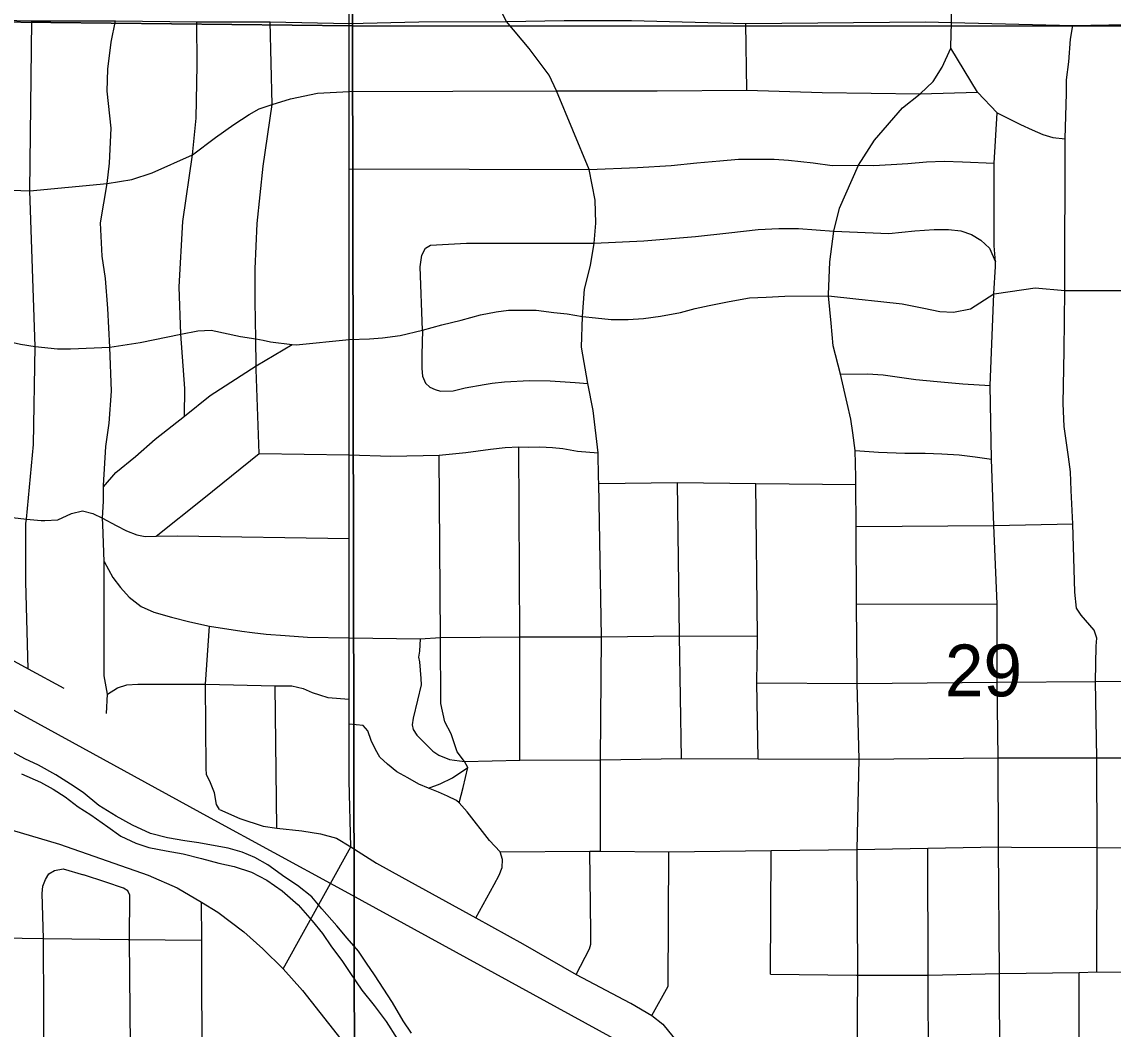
# Model space of a CAD drawing. Extents: x 0 to 34, y 0 to 22.
# Drawn here: x 3.784 to 4.664, y 18.692 to 19.505 of the extents above; entities that cross this region are included whole.
import ezdxf

# ---------------------------------------------------------------- set-up
doc = ezdxf.new("R2010")
doc.units = 0
for name, color, linetype in [('GM_X_City_Street', 7, 'Continuous'), ('GM_X_County_Road', 7, 'Continuous'), ('GM_X_Minor_River', 7, 'Continuous'), ('GM_X_Rail_Line', 7, 'Continuous'), ('GM_X_Section', 7, 'Continuous'), ('GM_X_Section_Text', 7, 'Continuous')]:
    doc.layers.add(name, color=color, linetype=linetype)

msp = doc.modelspace()

# ---------------------------------------------------------------- linework, layer by layer
at = {"layer": 'GM_X_City_Street'}
for p, q in [((4.36899, 19.44986), (4.36805, 19.50372)), ((4.45735, 19.03517), (4.57094, 19.03531)), ((3.98987, 18.85427), (3.98842, 18.96911)), ((4.38793, 18.73648), (4.3886, 18.83632)), ((3.89964, 18.76435), (3.9294, 18.76407)), ((4.38793, 18.73648), (4.45746, 18.73577)), ((4.27536, 18.71305), (4.29227, 18.7032))]:
    msp.add_line(p, q, dxfattribs=at)
for points in [[(4.21534, 19.44926), (4.20947, 19.46187), (4.19338, 19.48352), (4.17513, 19.50518), (4.16591, 19.52327), (4.16076, 19.54117), (4.15845, 19.55941), (4.15556, 19.60002), (4.1545, 19.61367), (4.15125, 19.6552), (4.15125, 19.65606), (4.15323, 19.70997), (4.15729, 19.74229), (4.16073, 19.77161), (4.16742, 19.83163), (4.16936, 19.86473), (4.16715, 19.89331), (4.16377, 19.93656), (4.1588, 19.97307), (4.15568, 20.0293), (4.1563, 20.06684)], [(3.55615, 19.50881), (3.61303, 19.50805), (3.6739, 19.50718), (3.73172, 19.50718), (3.79215, 19.50588), (3.85954, 19.50588), (3.92519, 19.50501), (3.98431, 19.50501), (4.04819, 19.5037), (4.10439, 19.50509), (4.17513, 19.50518), (4.22153, 19.5061), (4.27577, 19.50611), (4.36805, 19.50372), (4.51295, 19.50505), (4.53405, 19.50437), (4.63184, 19.50201), (4.6753, 19.50298), (4.75176, 19.50458), (4.76019, 19.50475), (4.80108, 19.50436), (4.86718, 19.50405), (4.91274, 19.50445)], [(3.78914, 18.9829), (3.7874, 19.05322), (3.7874, 19.10015), (3.78774, 19.10376), (3.79342, 19.16393), (3.79479, 19.24313), (3.79051, 19.36859), (3.79215, 19.50588)], [(3.84998, 19.13087), (3.85186, 19.16229), (3.85445, 19.18111), (3.85641, 19.20705), (3.8552, 19.24251), (3.85354, 19.27363), (3.85155, 19.29802), (3.84892, 19.31583), (3.8476, 19.34286), (3.85285, 19.37456), (3.85485, 19.39099), (3.85617, 19.41934), (3.85288, 19.449), (3.85354, 19.46681), (3.85617, 19.48857), (3.85954, 19.50588)], [(3.91532, 19.18672), (3.91562, 19.2092), (3.91249, 19.2531), (3.91103, 19.29109), (3.91409, 19.3439), (3.92183, 19.39777), (3.92481, 19.42732), (3.92557, 19.47017), (3.92519, 19.50501)], [(3.97549, 19.15676), (3.97323, 19.22437), (3.97319, 19.22747), (3.9729, 19.24936), (3.97243, 19.27938), (3.97243, 19.30569), (3.97402, 19.34237), (3.97881, 19.38861), (3.98616, 19.43823), (3.98431, 19.50501)], [(4.65121, 18.73849), (4.65155, 18.83884), (4.65114, 18.91116), (4.65026, 18.97268), (4.65062, 19.00126), (4.65133, 19.00769), (4.64919, 19.01412), (4.63847, 19.02627), (4.63491, 19.03198), (4.63348, 19.04483), (4.63198, 19.09987), (4.63062, 19.12697), (4.62991, 19.14197), (4.62848, 19.15411), (4.6249, 19.1784), (4.62419, 19.19697), (4.6249, 19.23983), (4.62534, 19.28832), (4.62573, 19.4106), (4.62669, 19.44761), (4.62669, 19.45815), (4.62866, 19.47264), (4.62998, 19.49108), (4.63184, 19.50201)], [(4.57279, 18.73709), (4.57177, 18.83936), (4.5717, 18.91116), (4.57083, 18.97212), (4.57094, 19.03531), (4.56807, 19.09855), (4.56615, 19.15221), (4.56519, 19.21161), (4.56822, 19.2856), (4.56961, 19.30758), (4.56935, 19.31144), (4.5685, 19.32438), (4.5685, 19.39101), (4.5709, 19.43152), (4.55484, 19.44835), (4.53342, 19.48379)], [(3.73239, 19.37081), (3.79051, 19.36859), (3.85285, 19.37456), (3.87275, 19.37788), (3.88933, 19.38318), (3.92183, 19.39777), (3.9404, 19.4117), (3.95499, 19.42231), (3.96759, 19.43027), (3.97555, 19.43491), (3.98616, 19.43823), (4.00075, 19.44287), (4.02264, 19.44751), (4.04819, 19.44884), (4.21534, 19.44926), (4.2966, 19.44926), (4.36899, 19.44986), (4.42963, 19.44809), (4.50866, 19.44693), (4.55484, 19.44835)], [(4.23637, 19.2673), (4.23792, 19.28927), (4.24287, 19.30844), (4.24584, 19.32655), (4.2472, 19.34247), (4.24658, 19.36103), (4.24164, 19.38577), (4.21534, 19.44926)], [(4.5709, 19.43152), (4.58977, 19.42208), (4.59896, 19.418), (4.60762, 19.41418), (4.61578, 19.41162), (4.62573, 19.4106)], [(4.57018, 19.28588), (4.60154, 19.29036), (4.62534, 19.28832), (4.68109, 19.28832), (4.75793, 19.28968), (4.77152, 19.29104), (4.78173, 19.29308), (4.79396, 19.29852), (4.82836, 19.32165), (4.85992, 19.3434), (4.89529, 19.36774), (4.92631, 19.38928), (4.97045, 19.41888)], [(4.0482, 19.3865), (4.24164, 19.38577), (4.28068, 19.38751), (4.30796, 19.38917), (4.32862, 19.39124), (4.34721, 19.39289), (4.3621, 19.39412), (4.39102, 19.39412), (4.40259, 19.3933), (4.42243, 19.39124), (4.43772, 19.38917), (4.45895, 19.38944), (4.47119, 19.38917), (4.48545, 19.38979), (4.49867, 19.39082), (4.51376, 19.39206), (4.52801, 19.39268), (4.54289, 19.39206), (4.5685, 19.39101)], [(4.10741, 19.25621), (4.10554, 19.30742), (4.10671, 19.3167), (4.10961, 19.32249), (4.11367, 19.32481), (4.14265, 19.32655), (4.24584, 19.32655), (4.28584, 19.32829), (4.32758, 19.33176), (4.35425, 19.33467), (4.37801, 19.33756), (4.39482, 19.33815), (4.41048, 19.33815), (4.43898, 19.33601), (4.48337, 19.33437), (4.50439, 19.33641), (4.52004, 19.33756), (4.53164, 19.33756), (4.54149, 19.33641), (4.55019, 19.3335), (4.55773, 19.32887), (4.56468, 19.32249), (4.56935, 19.31144)], [(4.23637, 19.2673), (4.24691, 19.26618), (4.25937, 19.26493), (4.27307, 19.26493), (4.28552, 19.26555), (4.29923, 19.26742), (4.31542, 19.27053), (4.32725, 19.27365), (4.33846, 19.27614), (4.35465, 19.27925), (4.37104, 19.28233), (4.38455, 19.28299), (4.39949, 19.28361), (4.43483, 19.28402)], [(4.43483, 19.28402), (4.45671, 19.28152), (4.47711, 19.27948), (4.49411, 19.27744), (4.51178, 19.27404), (4.5247, 19.27132), (4.53558, 19.27065), (4.54918, 19.27336), (4.56822, 19.2856), (4.57018, 19.28588)], [(3.97882, 19.24812), (3.98473, 19.24687), (4.00228, 19.24474), (4.00529, 19.24438), (4.0482, 19.24874), (4.06445, 19.24936), (4.07503, 19.24999), (4.08936, 19.25185), (4.10741, 19.25621), (4.12299, 19.26057), (4.13855, 19.26431), (4.15412, 19.26866), (4.16658, 19.27116), (4.17654, 19.2724), (4.18713, 19.2724), (4.19896, 19.2724), (4.21328, 19.27053), (4.22387, 19.26929), (4.23637, 19.2673)], [(3.55853, 19.2406), (3.61671, 19.24117), (3.63038, 19.24189), (3.64969, 19.24687), (3.6746, 19.25559), (3.68581, 19.26119), (3.69328, 19.26306), (3.70636, 19.26244), (3.72331, 19.26305), (3.73259, 19.26108), (3.7512, 19.2531), (3.76615, 19.24874), (3.78296, 19.245), (3.79479, 19.24313), (3.81285, 19.24127), (3.82344, 19.24127), (3.8552, 19.24251), (3.87948, 19.24624), (3.91249, 19.2531), (3.92619, 19.25559), (3.93678, 19.25621), (3.96045, 19.25123), (3.9729, 19.24936), (3.97882, 19.24812)], [(4.24936, 19.13745), (4.24901, 19.15729), (4.24503, 19.19146), (4.2407, 19.21318), (4.23551, 19.24244), (4.23637, 19.2673)], [(4.10741, 19.25621), (4.10666, 19.23636), (4.10666, 19.2252), (4.1072, 19.21921), (4.10965, 19.21349), (4.11319, 19.21022), (4.11755, 19.20832), (4.1219, 19.20696), (4.13198, 19.20723), (4.14179, 19.20968), (4.15704, 19.2124), (4.16357, 19.21349), (4.17338, 19.21458), (4.19353, 19.21567), (4.21014, 19.21539), (4.23056, 19.21403), (4.2407, 19.21318)], [(3.84992, 19.12986), (3.85987, 19.14136), (3.87583, 19.15438), (3.89179, 19.16824), (3.91532, 19.18672), (3.9359, 19.20353), (3.97319, 19.22747), (4.00228, 19.24474)], [(4.44435, 19.22076), (4.46633, 19.221), (4.47898, 19.22017), (4.5051, 19.21637), (4.52238, 19.21469), (4.54303, 19.213), (4.56519, 19.21161)], [(3.89241, 19.09004), (3.9309, 19.12069), (3.97549, 19.15676), (4.04821, 19.15554)], [(4.04821, 19.15554), (4.08187, 19.1547), (4.12071, 19.15528), (4.14228, 19.15758), (4.16213, 19.16017), (4.17393, 19.1616), (4.18486, 19.16218), (4.19292, 19.16189), (4.20183, 19.16218), (4.21219, 19.1616), (4.22053, 19.16074), (4.23233, 19.15872), (4.24901, 19.15729)], [(4.1369, 18.87473), (4.14001, 18.88719), (4.1438, 18.90337), (4.14123, 18.90808), (4.13514, 18.91589), (4.13029, 18.93045), (4.12543, 18.94016), (4.12197, 18.95506), (4.12174, 19.00821), (4.12071, 19.15528)], [(4.18589, 18.90913), (4.18569, 19.00871), (4.18486, 19.16218)], [(4.45639, 19.15917), (4.47518, 19.15779), (4.49625, 19.15695), (4.51268, 19.15695), (4.52617, 19.15653), (4.54008, 19.15569), (4.55314, 19.154), (4.56615, 19.15221)], [(3.50162, 19.14001), (3.55769, 19.11108), (3.61689, 19.07725), (3.66184, 19.05188), (3.73395, 19.01316), (3.78914, 18.9829), (3.81807, 18.96732)], [(3.84945, 19.09956), (3.84927, 19.10456), (3.84992, 19.11818), (3.84992, 19.12986), (3.84998, 19.13087)], [(4.25079, 18.83584), (4.2508, 18.90964), (4.25163, 19.00871), (4.24945, 19.13248), (4.24936, 19.13745)], [(4.24945, 19.13248), (4.31295, 19.13344), (4.37627, 19.13249), (4.45687, 19.13161)], [(4.31623, 18.91068), (4.3146, 19.0097), (4.31295, 19.13344)], [(4.37754, 19.00727), (4.37757, 19.0092), (4.37627, 19.13249)], [(3.67448, 19.10537), (3.68594, 19.1115), (3.69094, 19.11317), (3.69815, 19.11428), (3.71425, 19.11261), (3.73321, 19.11009), (3.78774, 19.10376), (3.79975, 19.10262), (3.80253, 19.10262), (3.81307, 19.10317), (3.82418, 19.10817), (3.83306, 19.11039), (3.84139, 19.10817), (3.84927, 19.10456), (3.86026, 19.09873), (3.86859, 19.09429), (3.87692, 19.09096), (3.88358, 19.08985), (3.89241, 19.09004), (3.90968, 19.09041), (4.04821, 19.08819)], [(3.85251, 18.94692), (3.85316, 18.9625), (3.85057, 18.97742), (3.85057, 19.06953), (3.84945, 19.09956)], [(4.45709, 19.09793), (4.56807, 19.09855), (4.63198, 19.09987)], [(3.85057, 19.06953), (3.85752, 19.05662), (3.86371, 19.04867), (3.87077, 19.04073), (3.88049, 19.03337), (3.89049, 19.02865), (3.90492, 19.02453), (3.91964, 19.021), (3.93554, 19.01747), (3.96145, 19.01335), (3.96999, 19.01217), (3.98117, 19.01099), (3.99648, 19.00981), (4.01444, 19.00864), (4.04822, 19.00805), (4.10538, 19.00722), (4.12174, 19.00821), (4.18569, 19.00871), (4.25163, 19.00871), (4.3146, 19.0097), (4.37757, 19.0092)], [(3.94367, 18.86951), (3.9411, 18.87358), (3.93939, 18.8829), (3.9357, 18.89219), (3.93299, 18.89733), (3.9327, 18.9028), (3.93231, 18.97062), (3.93554, 19.01747)], [(4.10538, 19.00722), (4.10474, 18.99716), (4.10396, 18.99246), (4.10474, 18.98854), (4.10592, 18.97524), (4.10631, 18.97015), (4.10318, 18.95762), (4.09965, 18.94315), (4.09887, 18.93767), (4.09965, 18.93414), (4.10279, 18.92945), (4.1157, 18.91653), (4.1204, 18.9134), (4.12901, 18.90988), (4.14123, 18.90808)], [(4.37802, 18.91047), (4.377, 18.97157), (4.37754, 19.00727)], [(4.377, 18.97157), (4.4579, 18.9712), (4.57083, 18.97212), (4.65026, 18.97268), (4.75912, 18.97379), (4.76412, 18.9799), (4.83411, 18.9799), (4.9213, 18.9799), (5.06741, 18.98086), (5.2073, 18.98068), (5.26798, 18.98362)], [(3.85316, 18.9625), (3.86121, 18.96767), (3.86892, 18.97008), (3.87759, 18.97056), (3.93231, 18.97062), (3.98842, 18.96911), (4.00191, 18.96911), (4.01106, 18.96719), (4.01829, 18.96381), (4.02408, 18.96189), (4.03082, 18.95996), (4.04822, 18.95851)], [(4.15031, 18.78206), (4.16502, 18.80883), (4.16916, 18.81642), (4.17158, 18.82263), (4.17193, 18.82919), (4.16989, 18.83539), (4.16123, 18.84437), (4.14329, 18.86748), (4.1369, 18.87473), (4.13466, 18.8768), (4.12742, 18.88025), (4.12017, 18.88335), (4.11223, 18.88663), (4.1043, 18.88991), (4.09533, 18.89508), (4.0867, 18.89992), (4.07911, 18.90613), (4.0729, 18.91165), (4.06945, 18.91786), (4.066, 18.9251), (4.06324, 18.93304), (4.05944, 18.93718), (4.04822, 18.93821)], [(4.14123, 18.90808), (4.18589, 18.90913), (4.2508, 18.90964), (4.31623, 18.91068), (4.37802, 18.91047), (4.45955, 18.91018), (4.5717, 18.91116), (4.65114, 18.91116), (4.75917, 18.91116), (4.83543, 18.91196), (4.92122, 18.91275), (4.96702, 18.91372)], [(4.11223, 18.88663), (4.12159, 18.89021), (4.13141, 18.89503), (4.1438, 18.90337)], [(3.94367, 18.86951), (3.96005, 18.86228), (3.97868, 18.856), (3.98987, 18.85427), (4.01004, 18.85219), (4.0251, 18.84979), (4.03792, 18.84643), (4.04943, 18.83941)], [(4.04943, 18.83941), (4.07021, 18.82608), (4.09062, 18.81486), (4.15031, 18.78206), (4.1881, 18.76118), (4.23126, 18.73624), (4.27451, 18.71354), (4.27536, 18.71305)], [(4.16989, 18.83539), (4.24235, 18.83593), (4.25079, 18.83584), (4.30612, 18.83525), (4.3886, 18.83632), (4.4579, 18.83722), (4.51483, 18.83829), (4.57177, 18.83936), (4.58228, 18.83901), (4.65155, 18.83884), (4.72759, 18.83852), (4.75872, 18.83927), (4.79711, 18.83902), (4.8355, 18.83877), (4.86353, 18.83848), (4.92138, 18.83961), (4.93209, 18.83982), (4.99657, 18.83982), (5.0671, 18.84102)], [(4.51575, 18.58733), (4.5151, 18.73573), (4.51483, 18.83829)], [(4.23126, 18.73624), (4.24206, 18.75697), (4.24299, 18.76069), (4.24299, 18.77058), (4.24235, 18.83593)], [(4.29227, 18.7032), (4.30535, 18.72685), (4.30612, 18.83525)], [(3.80128, 18.34846), (3.80281, 18.48855), (3.80266, 18.52022), (3.80222, 18.65031), (3.80149, 18.76525), (3.8005, 18.80167), (3.80094, 18.80751), (3.80319, 18.81291), (3.80589, 18.81741), (3.81039, 18.82011), (3.81743, 18.82169), (3.83381, 18.81671)], [(3.87041, 18.25538), (3.87147, 18.34807), (3.87188, 18.48816), (3.87235, 18.51932), (3.87193, 18.64982), (3.87087, 18.76461), (3.87115, 18.80026), (3.86962, 18.80382), (3.86606, 18.80585), (3.85183, 18.81094), (3.83381, 18.81671)], [(3.93441, 18.25538), (3.93543, 18.34807), (3.93626, 18.48783), (3.92966, 18.65027), (3.9294, 18.76407), (3.92913, 18.79477)], [(3.53684, 18.76219), (3.59853, 18.76219), (3.60496, 18.76721), (3.66386, 18.76637), (3.73238, 18.76637), (3.80149, 18.76525), (3.86989, 18.76462)], [(3.86989, 18.76462), (3.87087, 18.76461), (3.89964, 18.76435)], [(4.45746, 18.73577), (4.45845, 18.73576), (4.5151, 18.73573), (4.57279, 18.73709), (4.63708, 18.73786), (4.65121, 18.73849), (4.69957, 18.73802)], [(4.57342, 18.58505), (4.57334, 18.58812), (4.57279, 18.73709)], [(4.63749, 18.49189), (4.63676, 18.58099), (4.63708, 18.73786)], [(4.29227, 18.7032), (4.30126, 18.69624), (4.31629, 18.67767), (4.32554, 18.66724), (4.3496, 18.65375), (4.37104, 18.64189), (4.42511, 18.61261), (4.45749, 18.59706), (4.47929, 18.59182), (4.4991, 18.58733), (4.51575, 18.58733), (4.57334, 18.58812), (4.60426, 18.58495), (4.63676, 18.58099), (4.70114, 18.56913), (4.76394, 18.55767), (4.7972, 18.55099), (4.80901, 18.54878)]]:
    msp.add_lwpolyline(points, dxfattribs=at)
at = {"layer": 'GM_X_County_Road'}
msp.add_line((3.99502, 18.74102), (4.04943, 18.83941), dxfattribs=at)
for points in [[(4.04821, 19.08109), (4.04821, 19.08819), (4.04821, 19.09032), (4.04821, 19.15554), (4.0482, 19.24874), (4.0482, 19.3865), (4.04819, 19.44884), (4.04819, 19.5037), (4.04819, 19.57727), (4.04818, 19.70868), (4.04579, 19.80922), (4.04579, 19.81664), (4.04579, 19.8674), (4.04579, 19.89538), (4.04338, 19.99113), (4.04338, 20.00232), (4.04338, 20.11228), (4.04337, 20.18148), (4.04337, 20.1874), (4.0432, 20.19595), (4.04316, 20.19695)], [(4.53345, 19.48477), (4.53405, 19.50437), (4.53402, 19.57542), (4.534, 19.63893), (4.53398, 19.68236)], [(4.43487, 19.28504), (4.43592, 19.31133), (4.43898, 19.33601), (4.44366, 19.35467), (4.45895, 19.38944), (4.47196, 19.40958), (4.4944, 19.43559), (4.50866, 19.44693), (4.51913, 19.45676), (4.52653, 19.46849), (4.53342, 19.48379), (4.53345, 19.48477)], [(4.45676, 19.13752), (4.45639, 19.15917), (4.45445, 19.17351), (4.45282, 19.18442), (4.44973, 19.1973), (4.44435, 19.22076), (4.43863, 19.24355), (4.43686, 19.26182), (4.43483, 19.28402), (4.43487, 19.28504)], [(4.45785, 18.9772), (4.45735, 19.03517), (4.45709, 19.09793), (4.45687, 19.13161), (4.45676, 19.13752)], [(4.04822, 19.00012), (4.04822, 19.00805), (4.04821, 19.08109)], [(4.04943, 18.83941), (4.04822, 18.89253), (4.04822, 18.93821), (4.04822, 18.95851), (4.04822, 19.00012)], [(4.45749, 18.59706), (4.45845, 18.73576), (4.4579, 18.83722), (4.45955, 18.91018), (4.4579, 18.9712), (4.45785, 18.9772)], [(3.73173, 18.8659), (3.81438, 18.84158), (3.8859, 18.81635), (3.9095, 18.80636), (3.92913, 18.79477), (3.94229, 18.78652), (3.96316, 18.77064), (3.97843, 18.75711), (3.99502, 18.74102), (4.01059, 18.72341), (4.03848, 18.68789), (4.05192, 18.67038), (4.08613, 18.62566), (4.14833, 18.54791), (4.19368, 18.49025), (4.2156, 18.46467), (4.24299, 18.43832), (4.30015, 18.38362)]]:
    msp.add_lwpolyline(points, dxfattribs=at)
at = {"layer": 'GM_X_Minor_River'}
for points in [[(4.02621, 18.78923), (4.01804, 18.79889), (4.00645, 18.80824), (3.99633, 18.81491), (3.98246, 18.82469), (3.97195, 18.8306), (3.96178, 18.83498), (3.95044, 18.83825), (3.9372, 18.8408), (3.92697, 18.84253), (3.91561, 18.84428), (3.9016, 18.84646), (3.888, 18.85016), (3.87332, 18.85691), (3.86016, 18.86402), (3.84628, 18.87266), (3.83357, 18.88317), (3.82344, 18.88984), (3.81143, 18.8973), (3.79753, 18.90518), (3.78662, 18.91034), (3.77271, 18.91784)], [(3.78372, 18.89824), (3.79916, 18.89147), (3.80931, 18.88594), (3.81906, 18.87967), (3.82954, 18.87148), (3.83967, 18.86519), (3.85353, 18.85541), (3.86402, 18.84798), (3.87607, 18.84242), (3.88664, 18.83879), (3.90064, 18.83622), (3.91427, 18.83367), (3.92901, 18.82995), (3.94299, 18.82625), (3.95547, 18.82333), (3.96943, 18.81887), (3.98185, 18.81254), (3.99421, 18.80393), (4.00691, 18.79266), (4.01842, 18.77951), (4.02658, 18.76946), (4.03397, 18.75867), (4.0421, 18.74749), (4.04875, 18.73786)], [(4.09831, 18.68899), (4.09167, 18.699), (4.08322, 18.71361), (4.06847, 18.73594), (4.0622, 18.74557), (4.05555, 18.7552), (4.04664, 18.76564), (4.0381, 18.77569), (4.02621, 18.78923)], [(4.04875, 18.73786), (4.05835, 18.72361), (4.06836, 18.71125), (4.07799, 18.69852), (4.08682, 18.68428)]]:
    msp.add_lwpolyline(points, dxfattribs=at)
at = {"layer": 'GM_X_Rail_Line'}
msp.add_lwpolyline([(4.43224, 18.5911), (4.35401, 18.63374), (4.03896, 18.80642), (3.93636, 18.86252), (3.55446, 19.07184), (3.44627, 19.13121), (3.32905, 19.19548), (3.23414, 19.24733), (3.176, 19.27923), (3.12462, 19.30736), (3.02751, 19.36047), (2.90102, 19.42945), (2.74452, 19.51493), (2.65716, 19.56269), (2.57906, 19.60512), (2.43608, 19.68368), (2.39019, 19.70835), (2.24327, 19.78828)], dxfattribs=at)
at = {"layer": 'GM_X_Section'}
for points in [[(3.04368, 20.50725), (4.04262, 20.49916), (4.05087, 19.50181), (3.02863, 19.51298)], [(4.04262, 20.49916), (5.03178, 20.49467), (5.03707, 19.50155), (4.05087, 19.50181)], [(3.02863, 19.51298), (4.05087, 19.50181), (4.05276, 18.48869), (3.03099, 18.49904)], [(5.03707, 19.50155), (5.03965, 18.48463), (4.05276, 18.48869), (4.05087, 19.50181)]]:
    msp.add_lwpolyline(points, close=True, dxfattribs=at)

# ---------------------------------------------------------------- texts
at = {"layer": 'GM_X_Section_Text'}
msp.add_text('29', height=0.041856, rotation=0.00001, dxfattribs=at).set_placement((4.52868, 18.96074))

doc.saveas('drawing.dxf')
